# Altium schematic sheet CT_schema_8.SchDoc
size 226 x 144 mm
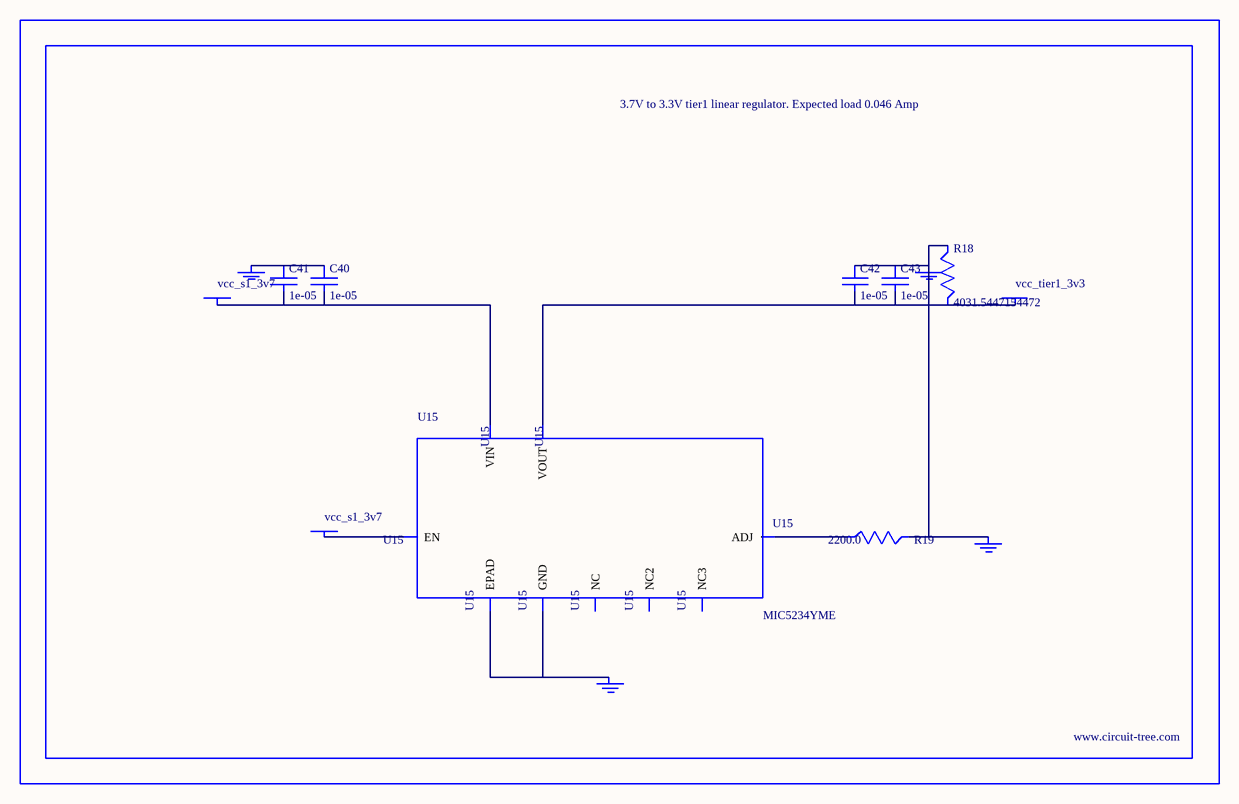
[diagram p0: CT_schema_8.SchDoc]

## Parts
BORDER7  (no value)
C40  1e-05  [C1210]
C41  1e-05  [C1210]
C42  1e-05  [C1210]
C43  1e-05  [C1210]
GND_INSTANCE_7_0  (no value)
GND_INSTANCE_7_1  (no value)
GND_INSTANCE_7_2  (no value)
GND_INSTANCE_7_3  (no value)
POWER_INSTANCE_7_0  vcc_tier1_3v3
POWER_INSTANCE_7_1  vcc_s1_3v7
POWER_INSTANCE_7_2  vcc_s1_3v7
R18  4031.5447154472  [R0603]
R19  2200.0  [R0603]
U15  MIC5234YME  [SOIC-8_EP]

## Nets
NetC40_1: C40.1 C41.1 GND_INSTANCE_7_3.0(GND)
NetC40_2: C40.2 C41.2 POWER_INSTANCE_7_2.0(PWR) U15.8(VIN)
NetC42_1: C42.1 C43.1 GND_INSTANCE_7_0.0(GND) GND_INSTANCE_7_1.0(GND) R18.1 R19.2
NetC42_2: C42.2 C43.2 POWER_INSTANCE_7_0.0(PWR) R18.2 U15.1(VOUT)
NetGND_INSTANCE_7_2_0: GND_INSTANCE_7_2.0(GND) U15.7(GND) U15.EPAD
NetPOWER_INSTANCE_7_1_0: POWER_INSTANCE_7_1.0(PWR) U15.5(EN)
NetR19_1: R19.1 U15.4(ADJ)

Not connected (* = marked no-connect by the designer): U15 2(NC) 3(NC2) 6(NC3)

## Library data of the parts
BORDER7 = BORDER_PAGE7
C40-C43 = C1210C106K5PACTU
GND_INSTANCE_7_0-GND_INSTANCE_7_3 = GND
POWER_INSTANCE_7_0-POWER_INSTANCE_7_2 = PWR
R18 = R18
R19 = RC0603JR-072K2L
